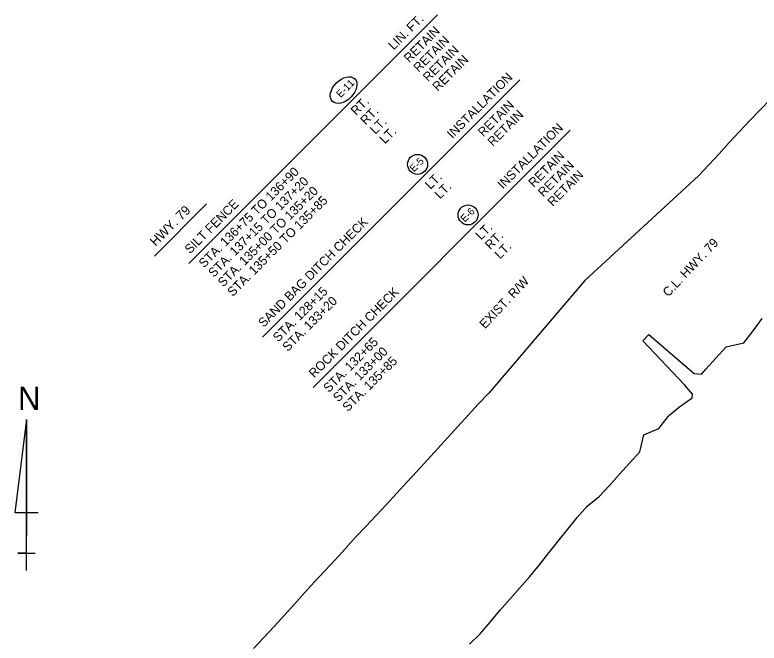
# Model space of a CAD drawing. Extents: x 1377291 to 1378879, y 1932405 to 1934097.
# Drawn here: x 1377488.7 to 1377981.8, y 1933226 to 1933642 of the extents above; entities that cross this region are included whole.
import ezdxf

# ---------------------------------------------------------------- set-up
doc = ezdxf.new("R2010")
doc.units = 0
for name, color, linetype in [('1', 7, 'Continuous'), ('44', 7, 'Continuous'), ('63', 7, 'Continuous'), ('R_Draft', 7, 'Continuous'), ('R_NO PLOT', 7, 'Continuous')]:
    doc.layers.add(name, color=color, linetype=linetype)

msp = doc.modelspace()

# ---------------------------------------------------------------- linework, layer by layer
at = {"layer": '1'}
for centre in [(1377755.46, 1933542.98), (1377788.93, 1933509.51)]:
    msp.add_circle(centre, 6.61, dxfattribs=at)
msp.add_ellipse((1377706.46, 1933592.16), major_axis=(7.44, 7.44), ratio=0.638788, dxfattribs=at)
at = {"layer": '44'}
for p, q in [((1377603.99, 1933477.37), (1377768.6, 1933641.98)), ((1377652.74, 1933428.62), (1377823.16, 1933599.04)), ((1377686.21, 1933395.15), (1377856.62, 1933565.57)), ((1377581.17, 1933482.25), (1377615.7, 1933516.79))]:
    msp.add_line(p, q, dxfattribs=at)
at = {"layer": '63'}
for p, q in [((1377496.34, 1933374), (1377488.65, 1933312.46)), ((1377496.34, 1933274), (1377496.34, 1933374)), ((1377496.34, 1933374), (1377496.34, 1933297.07)), ((1377488.65, 1933312.46), (1377504.04, 1933312.46)), ((1377496.34, 1933274), (1377496.34, 1933297.07)), ((1377496.34, 1933285.53), (1377490.58, 1933285.53)), ((1377490.58, 1933285.53), (1377502.11, 1933285.53)), ((1377496.34, 1933274), (1377496.34, 1933285.53))]:
    msp.add_line(p, q, dxfattribs=at)
at = {"layer": 'R_NO PLOT'}
for points in [[(1378032.08, 1933628.8), (1378023.82, 1933622.84), (1378017.02, 1933615.51), (1378010.21, 1933608.18), (1378003.34, 1933600.92), (1377996.38, 1933593.74), (1377989.58, 1933586.41), (1377982.61, 1933579.24), (1377975.66, 1933572.04), (1377968.8, 1933564.76), (1377962.03, 1933557.41), (1377955.24, 1933550.06), (1377948.47, 1933542.7), (1377941.65, 1933535.39)], [(1377941.65, 1933535.39), (1377866.37, 1933466.17), (1377802.58, 1933391.45), (1377795.68, 1933384.21), (1377788.93, 1933376.84), (1377782.19, 1933369.44), (1377775.46, 1933362.04), (1377768.75, 1933354.63), (1377762.01, 1933347.24), (1377755.23, 1933339.89), (1377748.42, 1933332.56), (1377741.68, 1933325.18), (1377734.88, 1933317.85), (1377728.11, 1933310.49), (1377721.19, 1933303.27), (1377714.32, 1933296), (1377707.61, 1933288.58), (1377700.9, 1933281.17), (1377694.08, 1933273.85), (1377687.27, 1933266.53), (1377680.49, 1933259.18), (1377673.85, 1933251.69), (1377667.12, 1933244.3), (1377660.34, 1933236.95), (1377653.52, 1933229.64), (1377646.7, 1933222.33)], [(1377959.93, 1933422.1), (1377971.59, 1933424.86), (1377977.76, 1933432.8), (1377983.83, 1933440.81)], [(1377932.36, 1933396.98), (1377904.63, 1933426.07), (1377908.75, 1933430.43), (1377938.72, 1933404.58), (1377943.5, 1933404), (1377946.36, 1933407.41)], [(1377946.36, 1933407.41), (1377953.17, 1933414.74), (1377959.93, 1933422.1)], [(1377789.97, 1933225.25), (1377797.07, 1933232.31), (1377803.6, 1933239.89), (1377809.99, 1933247.61), (1377816.58, 1933255.13), (1377823.22, 1933262.62), (1377829.83, 1933270.13), (1377836.27, 1933277.8), (1377842.48, 1933285.68), (1377848.72, 1933293.54), (1377855.03, 1933301.33), (1377861.21, 1933309.24), (1377867.88, 1933316.69), (1377875.74, 1933323.04), (1377882.55, 1933330.36), (1377889.25, 1933337.78), (1377895.96, 1933345.2), (1377902.69, 1933352.6), (1377905.32, 1933363.83), (1377915.42, 1933368.07), (1377921.53, 1933376.05), (1377921.82, 1933376.42), (1377929.1, 1933382.46), (1377937.48, 1933388.31), (1377937.59, 1933390.74), (1377932.36, 1933396.98)]]:
    msp.add_lwpolyline(points, dxfattribs=at)

# ---------------------------------------------------------------- texts
at = {"layer": '1'}
for s, p in [('E-11', (1377704.45, 1933586.82)), ('E-5 ', (1377753.05, 1933537.61)), ('E-6 ', (1377786.73, 1933504.36))]:
    msp.add_text(s, height=4.8, rotation=45, dxfattribs=at).set_placement(p)
at = {"layer": '44'}
for s, height, p in [('LIN. FT.', 6, (1377739.68, 1933618.37)), ('RETAIN', 6, (1377749.92, 1933609.97)), ('RETAIN', 6, (1377756.25, 1933603.64)), ('RETAIN', 6, (1377762.58, 1933597.32)), ('RETAIN', 6, (1377768.91, 1933590.99)), ('INSTALLATION', 6, (1377778.53, 1933559.72)), ('RT.', 6, (1377714.74, 1933575.02)), ('RETAIN', 6, (1377799.03, 1933560.86)), ('RT.', 6, (1377721.07, 1933568.69)), ('RETAIN', 6, (1377805.36, 1933554.53)), ('LT.', 6, (1377727.49, 1933562.47)), ('INSTALLATION', 6, (1377812, 1933526.25)), ('LT.', 6, (1377733.82, 1933556.14)), ('RETAIN', 6, (1377832.5, 1933527.39)), ('RETAIN', 6, (1377838.83, 1933521.07)), ('STA. 136+75 TO 136+90', 6, (1377614.03, 1933474.11)), ('RETAIN', 6, (1377845.15, 1933514.74)), ('STA. 137+15 TO 137+20', 6, (1377620.36, 1933467.78)), ('LT.', 6, (1377763.95, 1933526.01)), ('LT.', 6, (1377770.28, 1933519.68)), ('STA. 135+00 TO 135+20', 6, (1377626.68, 1933461.45)), ('SILT FENCE      ', 6, (1377604.72, 1933483.41)), ('STA. 135+50 TO 135+85', 6, (1377633.01, 1933455.12)), ('HWY. 79', 6.25, (1377581.92, 1933488.35)), ('SAND BAG DITCH CHECK', 6, (1377653.47, 1933434.66)), ('LT.', 6, (1377797.42, 1933492.55)), ('RT.', 6, (1377803.64, 1933486.12)), ('LT.', 6, (1377810.07, 1933479.89)), ('STA. 128+15', 6, (1377663.14, 1933425)), ('ROCK DITCH CHECK', 6, (1377686.94, 1933401.2)), ('STA. 133+20', 6, (1377669.47, 1933418.67)), ('STA. 132+65', 6, (1377696.61, 1933391.53)), ('STA. 133+00', 6, (1377702.93, 1933385.2)), ('STA. 135+85', 6, (1377709.26, 1933378.87))]:
    msp.add_text(s, height=height, rotation=45, dxfattribs=at).set_placement(p)
at = {"layer": '63'}
msp.add_text('N', height=15.38, rotation=360, dxfattribs=at).set_placement((1377490.71, 1933380.41))
at = {"layer": 'R_Draft'}
for s, p in [('C.L. HWY. 79', (1377921.6, 1933454.85)), ('EXIST. R/W', (1377800.18, 1933433.74))]:
    msp.add_text(s, height=6, rotation=46.6607, dxfattribs=at).set_placement(p)

doc.saveas('drawing.dxf')
